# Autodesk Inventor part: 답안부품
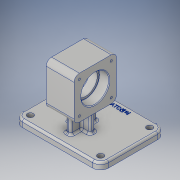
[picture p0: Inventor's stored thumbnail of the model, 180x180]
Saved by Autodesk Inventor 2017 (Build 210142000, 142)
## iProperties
Part Number: 답안부품
Material: 알루미늄 6061
Document SubType Name: Modeling
Designer: 222
Mass: 683.214 g
Surface Area: 542.794 cm^2
Volume: 253.042 cm^3
Density: 2.7 g/cm^3
Appearance: 알루미늄 - 평지
Author: 222
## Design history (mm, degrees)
sketch "스케치1"
  geometry: L1 (-32, 32)-(32, 32); L2 (32, 32)-(32, -32); L3 (32, -32)-(-32, -32); L4 (-32, -32)-(-32, 32); L5 (-32, 32)-(32, -32); L6 (32, 32)-(-32, -32); 1 further point
  constraints: 12 end point, 2 midpoint, 2 parallel, 1 horizontal, 1 perpendicular
  dimensions: "d0" = 64 distance of L2.end L3.end; "d1" = 64 distance of L1.end L2.end
extrude "돌출1" new body sketch "스케치1" stored distance "d2" = 42; taper "d3" = 0 deg
sketch "스케치2"
  geometry: C1 r 21 at (0, 0); 1 further point
  constraints: 1 centre point, 1 coincident
  dimensions: "d4" = 42 diameter of C1
extrude "돌출2" cut sketch "스케치2" distance "d5" = 15; taper "d6" = 0 deg
sketch "스케치3"
  geometry: C1 r 21 at (0, 0) reference; C2 r 18 at (0, 0); 1 further point
  constraints: 1 centre point, 1 coincident
  dimensions: "d7" = 36 diameter of C2
extrude "돌출3" cut sketch "스케치3" distance "d8" = 12; taper "d9" = 0 deg
fillet "모깎기1" dims "d10" = 8
sketch "스케치4"
  geometry: A1 r 8 centre (-24, 24) between (-24, 32) and (-32, 24) reference; A2 r 8 centre (24, 24) between (32, 24) and (24, 32) reference; A3 r 8 centre (24, -24) between (24, -32) and (32, -24) reference; A4 r 8 centre (-24, -24) between (-32, -24) and (-24, -32) reference; 5 further points
  constraints: 4 coincident
hole "구멍1" sketch "스케치4" at (-24, 24), (24, 24), (24, -24), (-24, -24) diameter "d11" = 3.242; stored, may be unused: countersink angle "d15" = 90 deg, drill point angle "d17" = 118 deg; dims "d12" = 8, "d13" = 4, "d14" = 2, "d16" = 10
node "작업 평면1"
sketch "스케치5"
  geometry: L1 (0, 0)-(0, -62); L2 (0, -62)-(65, -62); L3 (65, -62)-(65, 36); L4 (65, 36)-(-65, 36); L5 (-65, 36)-(-65, -62); L6 (-65, -62)-(0, -62)
  constraints: 12 end point, 3 perpendicular, 1 point on line, 1 vertical
  dimensions: "d19" = 62 distance of L1.start L1.end; "d20" = 65 distance of L1.end L2.end; "d21" = 98 distance of L2.end L3.end; "d22" = 130 distance of L3.end L4.end; "d23" = 98 distance of L4.end L5.end
extrude "돌출4" join sketch "스케치5" distance "d24" = 10; taper "d25" = 0 deg
sketch "스케치6"
  geometry: L1 (-17, -4)-(17, -4); L2 (17, -4)-(17, 4); L3 (17, 4)-(-17, 4); L4 (-17, 4)-(-17, -4); L5 (-17, -4)-(17, 4); L6 (17, -4)-(-17, 4); L7 (-4, -20)-(4, -20); L8 (4, -20)-(4, 20); L9 (4, 20)-(-4, 20); L10 (-4, 20)-(-4, -20); L11 (-4, -20)-(4, 20); L12 (4, -20)-(-4, 20); 1 further point
  constraints: 24 end point, 4 midpoint, 4 parallel, 2 horizontal, 2 perpendicular
  dimensions: "d26" = 34 distance of L3.end L2.end; "d27" = 8 distance of L2.end L1.end; "d28" = 8 distance of L9.end L8.end; "d29" = 40 distance of L8.end L7.end
extrude "돌출5" join sketch "스케치6" stored distance "d30" = 10; taper "d31" = 0 deg
fillet "모깎기2" dims "d32" = 12
sketch "스케치7"
  geometry: A1 r 12 centre (-53, 50) between (-53, 62) and (-65, 50) reference; A2 r 12 centre (53, 50) between (65, 50) and (53, 62) reference; A3 r 12 centre (53, -24) between (53, -36) and (65, -24) reference; A4 r 12 centre (-53, -24) between (-65, -24) and (-53, -36) reference; 5 further points
  constraints: 4 coincident
hole "구멍2" sketch "스케치7" at (-53, 50), (53, 50), (53, -24), (-53, -24) diameter "d33" = 9; stored, may be unused: countersink angle "d37" = 90 deg, drill point angle "d39" = 0 deg; dims "d34" = 8, "d35" = 4, "d36" = 2, "d38" = 10
fillet "모깎기3" dims "d40" = 0.3
fillet "모깎기4" dims "d41" = 3
fillet "모깎기5" dims "d42" = 3
fillet "모깎기6" dims "d43" = 3
fillet "모깎기7" dims "d44" = 3
chamfer "모따기1" distance "d45" = 1; stored, may be unused: second distance "d46" = 2, angle "d47" = 45 deg
sketch "스케치8"
  geometry: L1 (53, 62)-(-53, 62) reference; L2 (65, -24)-(65, 50) reference; 2 further points
  constraints: 1 other
  dimensions: "d48" = 10 distance from line of L1 point (0, 52); "d49" = 65 distance from line of L2 point (0, 52)
feature "엠보싱1" sketch "스케치8" dims "d0" = 64, "d1" = 64, "d50" = 0.5, "d51" = 0
sketch "스케치9"
  geometry: C1 r 21 at (0, 0); 1 further point
  constraints: 1 centre point, 1 coincident
  dimensions: "d52" = 42 diameter of C1
extrude "돌출6" cut sketch "스케치9" distance "d53" = 15; taper "d54" = 0 deg
chamfer "모따기2" distance "d55" = 1; stored, may be unused: second distance "d56" = 2, angle "d57" = 45 deg
fillet "모깎기8" dims "d58" = 0.3
node "솔리드1"
mirror "미러2"
